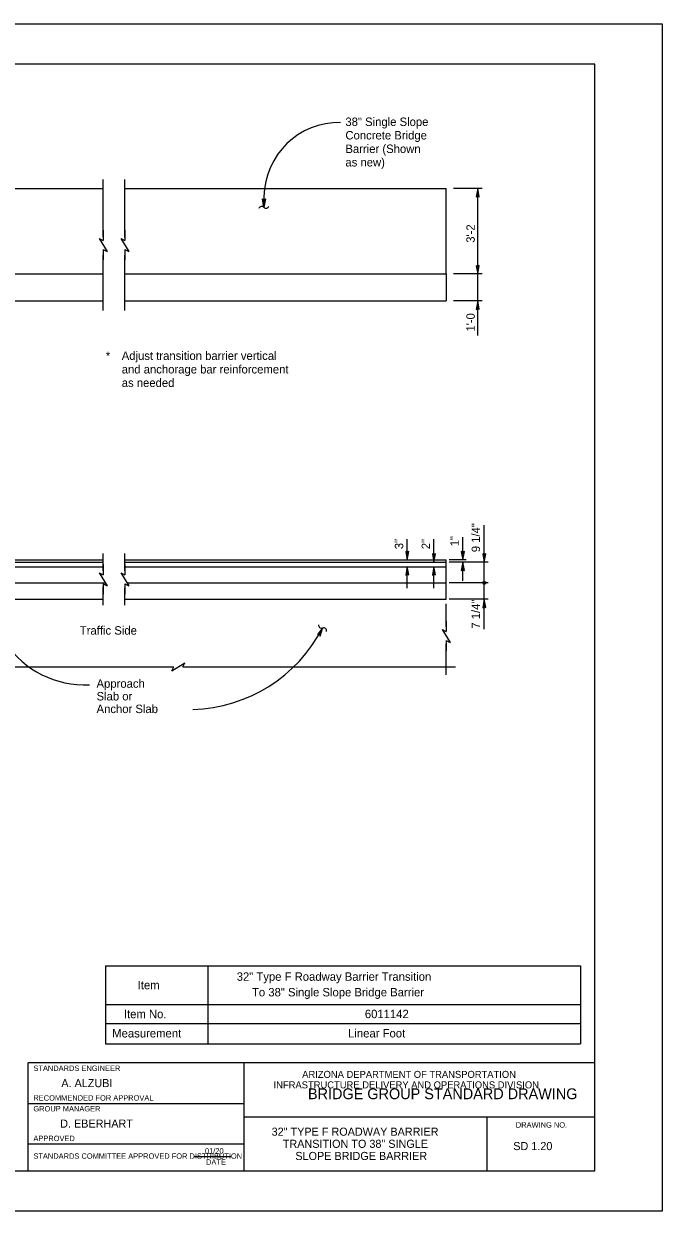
# Model space of a CAD drawing. Extents: x 0 to 2.83, y -0.03 to 1.83.
# Drawn here: x 1.848 to 2.833, y 0 to 1.833 of the extents above; entities that cross this region are included whole.
import ezdxf

# ---------------------------------------------------------------- set-up
doc = ezdxf.new("R2010")
doc.units = 0
for name, color, linetype in [('50', 7, 'Continuous'), ('54', 7, 'Continuous'), ('55', 7, 'Continuous'), ('57', 7, 'Continuous'), ('62', 7, 'Continuous'), ('63', 7, 'Continuous')]:
    doc.layers.add(name, color=color, linetype=linetype)

msp = doc.modelspace()

# ---------------------------------------------------------------- linework, layer by layer
at = {"layer": '50'}
for p, q in [((1.5072, 1.5789), (1.9702, 1.5789)), ((2.0036, 1.5789), (2.5, 1.5789)), ((2.5, 1.447), (2.5, 1.5789)), ((1.5072, 1.447), (1.9702, 1.447)), ((2.0036, 1.447), (2.5, 1.447)), ((2.5, 1.447), (2.5, 1.4053)), ((1.5072, 1.4053), (1.9702, 1.4053)), ((2.0036, 1.4053), (2.5, 1.4053)), ((0.8822, 1.0056), (1.9702, 1.0056)), ((1.5072, 0.9951), (1.9702, 0.9951)), ((1.5141, 1.0021), (1.9702, 1.0021)), ((2.0036, 1.0056), (2.5, 1.0056)), ((2.0036, 1.0021), (2.5, 1.0021)), ((2.0036, 1.0021), (2.5, 1.0021)), ((2.0036, 0.9951), (2.5, 0.9951)), ((2.5, 0.9448), (2.5, 1.0056)), ((0.8822, 0.9696), (1.9736, 0.97)), ((2.007, 0.97), (2.5, 0.97)), ((0.8822, 0.9448), (1.9702, 0.9448)), ((2.0036, 0.9448), (2.5, 0.9448))]:
    msp.add_line(p, q, dxfattribs=at)
at = {"layer": '54'}
for points in [[(2.5484, 1.5789), (2.546, 1.5659), (2.5484, 1.5674), (2.5508, 1.5661)], [(2.5484, 1.447), (2.5508, 1.46), (2.5484, 1.4585), (2.546, 1.4598)], [(2.5484, 1.4053), (2.546, 1.3923), (2.5484, 1.3938), (2.5508, 1.3925)], [(2.4397, 1.0056), (2.442, 1.0186), (2.4397, 1.0171), (2.4373, 1.0184)], [(2.4809, 1.0021), (2.4832, 1.0151), (2.4809, 1.0136), (2.4785, 1.015)], [(2.5255, 1.0056), (2.5279, 1.0186), (2.5255, 1.0171), (2.5231, 1.0184)], [(2.5586, 1.0021), (2.561, 1.0151), (2.5586, 1.0136), (2.5562, 1.015)], [(2.4397, 0.9952), (2.4373, 0.9822), (2.4397, 0.9837), (2.4421, 0.9823)], [(2.4808, 0.9952), (2.4785, 0.9822), (2.4808, 0.9837), (2.4832, 0.9823)], [(2.5255, 1.0021), (2.5231, 0.9891), (2.5255, 0.9906), (2.5279, 0.9893)], [(2.5586, 0.9448), (2.5562, 0.9318), (2.5586, 0.9333), (2.561, 0.932)]]:
    msp.add_lwpolyline(points, close=True, dxfattribs=at)
at = {"layer": '55'}
for p, q in [((1.9702, 1.5046), (1.9702, 1.5928)), ((2.0036, 1.5034), (2.0036, 1.5928)), ((2.5551, 1.5789), (2.5109, 1.5789)), ((2.5484, 1.447), (2.5484, 1.5789)), ((2.2184, 1.5666), (2.2184, 1.55)), ((1.9702, 1.5144), (1.9702, 1.4985)), ((2.0036, 1.5144), (2.0036, 1.4985)), ((1.964, 1.5016), (1.9702, 1.4985)), ((1.964, 1.5016), (1.9764, 1.4817)), ((1.9974, 1.5016), (2.0036, 1.4985)), ((1.9974, 1.5016), (2.0097, 1.4817)), ((1.9702, 1.4848), (1.9764, 1.4817)), ((1.9702, 1.4848), (1.9702, 1.4689)), ((1.9702, 1.3904), (1.9702, 1.4768)), ((2.0036, 1.4848), (2.0097, 1.4817)), ((2.0036, 1.4848), (2.0036, 1.4689)), ((2.0036, 1.3904), (2.0036, 1.476)), ((2.5551, 1.447), (2.5109, 1.447)), ((2.5484, 1.352), (2.5484, 1.447)), ((2.5551, 1.4053), (2.5109, 1.4053)), ((2.5586, 1.0021), (2.5586, 1.0591)), ((2.4397, 1.0056), (2.4397, 1.0378)), ((2.4809, 1.0021), (2.4809, 1.0378)), ((2.5255, 1.0056), (2.5255, 1.0408)), ((1.9702, 0.9889), (1.9702, 1.0157)), ((2.0036, 0.9885), (2.0036, 1.0157)), ((1.9702, 0.9983), (1.9702, 0.9824)), ((2.0036, 0.9983), (2.0036, 0.9824)), ((2.4397, 0.9621), (2.4397, 0.9952)), ((2.4808, 0.9621), (2.4808, 0.9952)), ((2.5308, 1.0056), (2.5043, 1.0056)), ((2.5644, 1.0021), (2.5043, 1.0021)), ((2.5255, 0.9734), (2.5255, 1.0021)), ((2.5586, 0.9448), (2.5586, 1.0021)), ((1.964, 0.9854), (1.9702, 0.9824)), ((1.964, 0.9854), (1.9764, 0.9656)), ((1.9974, 0.9854), (2.0036, 0.9824)), ((1.9974, 0.9854), (2.0097, 0.9656)), ((1.9702, 0.9686), (1.9764, 0.9656)), ((1.9702, 0.9686), (1.9702, 0.9527)), ((1.9702, 0.9357), (1.9702, 0.9638)), ((2.0036, 0.9686), (2.0097, 0.9656)), ((2.0036, 0.9686), (2.0036, 0.9527)), ((2.0036, 0.9357), (2.0036, 0.9618)), ((2.5644, 0.97), (2.5043, 0.97)), ((2.5, 0.9029), (2.5, 0.938)), ((2.5644, 0.9448), (2.5043, 0.9448)), ((2.5586, 0.8985), (2.5586, 0.9448)), ((2.5, 0.9108), (2.5, 0.8949)), ((2.4938, 0.898), (2.5, 0.8949)), ((2.4938, 0.898), (2.5061, 0.8781)), ((2.5, 0.8812), (2.5061, 0.8781)), ((2.5, 0.8812), (2.5, 0.8653)), ((2.5, 0.8284), (2.5, 0.8761)), ((2.0762, 0.8343), (2.0961, 0.8466)), ((2.093, 0.8404), (2.0961, 0.8466)), ((1.432, 0.8405), (2.0686, 0.8405)), ((2.0634, 0.8404), (2.0793, 0.8404)), ((2.0762, 0.8343), (2.0793, 0.8404)), ((2.093, 0.8404), (2.1089, 0.8404)), ((2.0968, 0.8405), (2.5142, 0.8405))]:
    msp.add_line(p, q, dxfattribs=at)
for points in [[(2.2184, 1.5499), (2.216, 1.5629), (2.2179, 1.5617), (2.2184, 1.553), (2.2189, 1.5617), (2.2207, 1.5629), (2.2184, 1.55)], [(2.2178, 1.5548), (2.2175, 1.5611), (2.2166, 1.5617), (2.2184, 1.5514), (2.2201, 1.5618), (2.2192, 1.5611), (2.219, 1.555)], [(2.309, 0.9004), (2.3009, 0.89), (2.3031, 0.8902), (2.3076, 0.8977), (2.304, 0.8897), (2.3051, 0.8878), (2.3089, 0.9003)], [(2.3062, 0.8964), (2.3031, 0.8908), (2.302, 0.8907), (2.3083, 0.8991), (2.305, 0.8891), (2.3045, 0.8901), (2.3071, 0.8956)]]:
    msp.add_lwpolyline(points, dxfattribs=at)
msp.add_circle((2.5586, 0.97), 0.00214, dxfattribs=at)
for centre, radius, start, end in [((2.3351, 1.5643), 0.1167, 89.1633, 178.8612), ((2.2151, 1.5466), 0.0047, 44.9538, 161.3599), ((2.2217, 1.5533), 0.0047, 224.9538, 341.3599), ((2.1013, 1.0085), 0.2341, 271.8499, 332.4926), ((2.3075, 0.9048), 0.0047, 171.3846, 287.7906), ((2.3104, 0.8959), 0.0047, 351.3846, 107.7906), ((1.9416, 0.96), 0.1473, 214.0105, 272.8594)]:
    msp.add_arc(centre, radius, start, end, dxfattribs=at)
at = {"layer": '57'}
for p, q in [((1.9739, 0.3789), (2.7072, 0.3789)), ((1.9739, 0.3789), (1.9739, 0.2585)), ((2.1316, 0.3789), (2.1316, 0.2585)), ((2.7072, 0.3789), (2.7072, 0.2585)), ((1.9739, 0.319), (2.7072, 0.319)), ((1.9739, 0.2898), (2.7072, 0.2898)), ((1.9739, 0.2585), (2.7072, 0.2585))]:
    msp.add_line(p, q, dxfattribs=at)
at = {"layer": '62'}
for p, q in [((2.7292, 0.2291), (1.8542, 0.2291)), ((1.8542, 0.0624), (1.8542, 0.2291)), ((2.1875, 0.2291), (2.1875, 0.0624)), ((2.5625, 0.1458), (2.5625, 0.0624)), ((2.111, 0.0843), (2.1675, 0.0843))]:
    msp.add_line(p, q, dxfattribs=at)
at = {"layer": '63'}
for p, q in [((0, 1.8333), (2.8333, 1.8333)), ((2.8333, 1.8333), (2.8333, 0)), ((1.8542, 0.1666), (2.1875, 0.1666)), ((2.1875, 0.1458), (2.7292, 0.1458)), ((1.8542, 0.1041), (2.1875, 0.1041)), ((2.8333, 0), (0, 0))]:
    msp.add_line(p, q, dxfattribs=at)
msp.add_lwpolyline([(2.7292, 1.7708), (0.1042, 1.7708), (0.1042, 0.0624), (2.7292, 0.0624)], close=True, dxfattribs=at)

# ---------------------------------------------------------------- texts
at = {"layer": '57'}
for s, height, p in [('38" Single Slope', 0.013021, (2.3442, 1.6755)), ('Concrete Bridge', 0.013021, (2.3442, 1.6547)), ('Barrier (Shown ', 0.013021, (2.3442, 1.6338)), ('as new)', 0.01302, (2.3442, 1.613)), ('*', 0.013, (1.9743, 1.3143)), ('Adjust transition barrier vertical ', 0.013021, (1.9989, 1.3143)), ('and anchorage bar reinforcement ', 0.013021, (1.9989, 1.2934)), ('as needed', 0.01302, (1.9989, 1.2726)), ('Traffic Side', 0.013021, (1.9342, 0.8902)), ('Approach', 0.01302, (1.96, 0.8082)), ('Slab or', 0.01302, (1.96, 0.7886)), ('Anchor Slab', 0.013025, (1.96, 0.7691)), ('32" Type F Roadway Barrier Transition ', 0.013021, (2.1764, 0.3558)), ('Item', 0.01302, (2.0235, 0.3427)), ('To 38" Single Slope Bridge Barrier', 0.013021, (2.2, 0.3317)), ('Item No.  ', 0.01302, (2.0022, 0.298)), ('6011142', 0.01302, (2.3742, 0.2981)), ('Measurement', 0.013021, (1.9842, 0.2683)), ('Linear Foot', 0.013021, (2.3484, 0.2683))]:
    msp.add_text(s, height=height, dxfattribs=at).set_placement(p)
for s, p in [("3'-2", (2.5439, 1.4952)), ("1'-0", (2.5439, 1.3581)), ('9 1/4"', (2.552, 1.0175)), ('3"', (2.4334, 1.0221)), ('2"', (2.4748, 1.0221)), ('1"', (2.5192, 1.0266)), ('7 1/4"', (2.552, 0.8995))]:
    msp.add_text(s, height=0.01297, rotation=90, dxfattribs=at).set_placement(p)
at = {"layer": '62'}
for s, height, p in [('STANDARDS ENGINEER', 0.008333, (1.8625, 0.2166)), ('     A. ALZUBI     ', 0.0125, (1.8824, 0.1916)), ('ARIZONA DEPARTMENT OF TRANSPORTATION', 0.010833, (2.2775, 0.2059)), ('INFRASTRUCTURE DELIVERY AND OPERATIONS DIVISION', 0.010833, (2.2333, 0.1897)), ('BRIDGE GROUP STANDARD DRAWING', 0.016667, (2.2864, 0.173)), ('RECOMMENDED FOR APPROVAL', 0.008333, (1.8625, 0.1708)), ('GROUP MANAGER', 0.008333, (1.8625, 0.1541)), ('     D. EBERHART      ', 0.0125, (1.8806, 0.1291)), ('32" TYPE F ROADWAY BARRIER', 0.0125, (2.2303, 0.1166)), ('DRAWING NO.', 0.008333, (2.6073, 0.1291)), ('APPROVED', 0.00833, (1.8625, 0.1083)), ('TRANSITION TO 38" SINGLE', 0.0125, (2.2475, 0.0979)), ('01/20', 0.00833, (2.1274, 0.0891)), ('SLOPE BRIDGE BARRIER', 0.0125, (2.2669, 0.0791)), (' SD 1.20 ', 0.0125, (2.5987, 0.0944)), ('STANDARDS COMMITTEE APPROVED FOR DISTRIBUTION', 0.008333, (1.8625, 0.081)), ('DATE', 0.00833, (2.129, 0.0718))]:
    msp.add_text(s, height=height, dxfattribs=at).set_placement(p)

doc.saveas('drawing.dxf')
